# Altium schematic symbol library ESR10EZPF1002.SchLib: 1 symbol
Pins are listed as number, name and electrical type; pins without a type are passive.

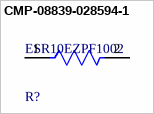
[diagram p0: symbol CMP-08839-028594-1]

## CMP-08839-028594-1
designator R?, comment ESR10EZPF1002
10kΩ ±1% 0.4W 0805 Anti-Surge Chip Resistor AEC-Q200; Max Power Dissipation: 400mW; Resistance: 10kR; Temperature Coefficient: 100ppm/°C
footprint FP-ESR10-IPC_C
footprint FP-ESR10-IPC_B
footprint FP-ESR10-IPC_A
footprint FP-ESR10-MFG
pins: 1, 2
